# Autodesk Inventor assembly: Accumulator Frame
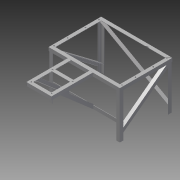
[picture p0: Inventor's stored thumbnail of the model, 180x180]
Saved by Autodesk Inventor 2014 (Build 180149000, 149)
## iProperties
Created: 2007-02
Part Number: Accumulator Frame
Document SubType Name: Assembly
Designer: Autodesk, Inc.
Mass: 65169.3 g
Surface Area: 27272.3 cm^2
Volume: 8291.26 cm^3
Density: 7.86 g/cm^3
_FrameDoc: Frame Assembly
_Version: 15.0.0
Title: Frame Skeleton
Author: Autodesk, Inc.
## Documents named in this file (20)
- C:\Users\iTools\Desktop\tutorial files\Tube and Pipe\Accumulator\Parts\Frame\Accumulator Frame.iam
- C:\Users\iTools\Desktop\tutorial files\Tube and Pipe\Accumulator\Parts\Frame\Skeleton0001.ipt
- C:\Users\iTools\Desktop\tutorial files\Tube and Pipe\Accumulator\Parts\Frame\ANSI L 2 x 2 x 1_4 00000001.ipt
- C:\Users\iTools\Desktop\tutorial files\Tube and Pipe\Accumulator\Parts\Frame\ANSI L 2 x 2 x 1_4 00000002.ipt
- C:\Users\iTools\Desktop\tutorial files\Tube and Pipe\Accumulator\Parts\Frame\ANSI L 2 x 2 x 1_4 00000003.ipt
- C:\Users\iTools\Desktop\tutorial files\Tube and Pipe\Accumulator\Parts\Frame\ANSI L 2 x 2 x 1_4 00000004.ipt
- C:\Users\iTools\Desktop\tutorial files\Tube and Pipe\Accumulator\Parts\Frame\ANSI L 2 x 2 x 1_4 00000005.ipt
- C:\Users\iTools\Desktop\tutorial files\Tube and Pipe\Accumulator\Parts\Frame\ANSI L 2 x 2 x 1_4 00000006.ipt
- C:\Users\iTools\Desktop\tutorial files\Tube and Pipe\Accumulator\Parts\Frame\ANSI L 2 x 2 x 1_4 00000007.ipt
- C:\Users\iTools\Desktop\tutorial files\Tube and Pipe\Accumulator\Parts\Frame\ANSI L 2 x 2 x 1_4 00000008.ipt
- C:\Users\iTools\Desktop\tutorial files\Tube and Pipe\Accumulator\Parts\Frame\ANSI L 2 x 2 x 1_4 00000009.ipt
- C:\Users\iTools\Desktop\tutorial files\Tube and Pipe\Accumulator\Parts\Frame\ANSI L 2 x 2 x 1_4 00000010.ipt
- C:\Users\iTools\Desktop\tutorial files\Tube and Pipe\Accumulator\Parts\Frame\ANSI L 2 x 2 x 1_4 00000011.ipt
- C:\Users\iTools\Desktop\tutorial files\Tube and Pipe\Accumulator\Parts\Frame\ANSI L 2 x 2 x 1_4 00000012.ipt
- C:\Users\iTools\Desktop\tutorial files\Tube and Pipe\Accumulator\Parts\Frame\ANSI L 2 x 2 x 1_4 00000013.ipt
- C:\Users\iTools\Desktop\tutorial files\Tube and Pipe\Accumulator\Parts\Frame\ANSI L 2 x 2 x 1_4 00000014.ipt
- C:\Users\iTools\Desktop\tutorial files\Tube and Pipe\Accumulator\Parts\Frame\ANSI L 2 x 2 x 1_4 00000015.ipt
- C:\Users\iTools\Desktop\tutorial files\Tube and Pipe\Accumulator\Parts\Frame\ANSI L 2 x 2 x 1_4 00000016.ipt
- C:\Users\iTools\Desktop\tutorial files\Tube and Pipe\Accumulator\Parts\Frame\ANSI L 2 x 2 x 1_4 00000019.ipt
- C:\Users\iTools\Desktop\tutorial files\Tube and Pipe\Accumulator\Parts\Frame\ANSI L 2 x 2 x 1_4 00000020.ipt
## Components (19 placed, 19 different names)
1. Frame Reference Model
2. ANSI L 2 x 2 x 1_4 00000001:1
3. ANSI L 2 x 2 x 1_4 00000002:1
4. ANSI L 2 x 2 x 1_4 00000003:1
5. ANSI L 2 x 2 x 1_4 00000004:1
6. ANSI L 2 x 2 x 1_4 00000005:1
7. ANSI L 2 x 2 x 1_4 00000006:1
8. ANSI L 2 x 2 x 1_4 00000007:1
9. ANSI L 2 x 2 x 1_4 00000008:1
10. ANSI L 2 x 2 x 1_4 00000009:1
11. ANSI L 2 x 2 x 1_4 00000010:1
12. ANSI L 2 x 2 x 1_4 00000011:1
13. ANSI L 2 x 2 x 1_4 00000012:1
14. ANSI L 2 x 2 x 1_4 00000013:1
15. ANSI L 2 x 2 x 1_4 00000014:1
16. ANSI L 2 x 2 x 1_4 00000015:1
17. ANSI L 2 x 2 x 1_4 00000016:1
18. ANSI L 2 x 2 x 1_4 00000019:1
19. ANSI L 2 x 2 x 1_4 00000020:1
